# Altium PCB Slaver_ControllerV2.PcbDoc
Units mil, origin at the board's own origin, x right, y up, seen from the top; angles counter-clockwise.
Board outline 1904 x 574 mil, 4 copper layers (Top Layer, GND, PWR, Bottom Layer), stack 30.634 mil thick; 85 components, 57 nets, 252 pads, 104 vias.
Unrouted connection lines stored in the file: 1.
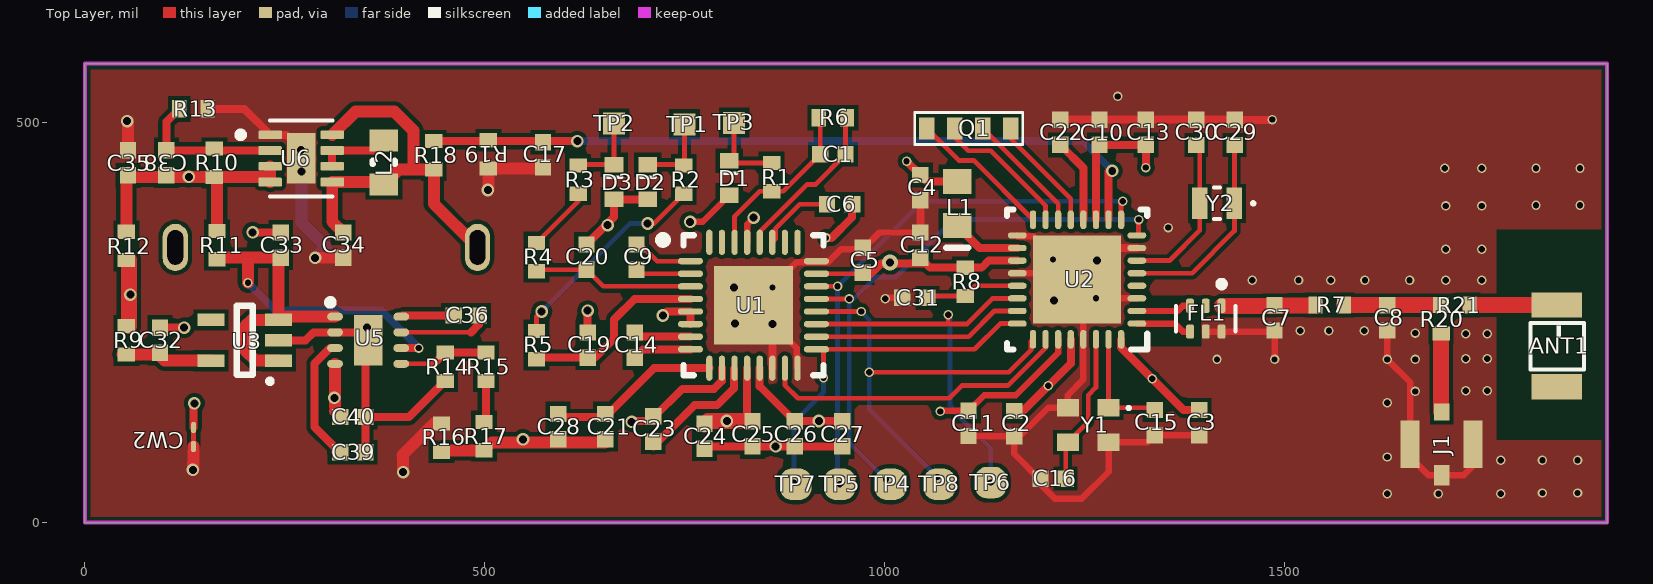
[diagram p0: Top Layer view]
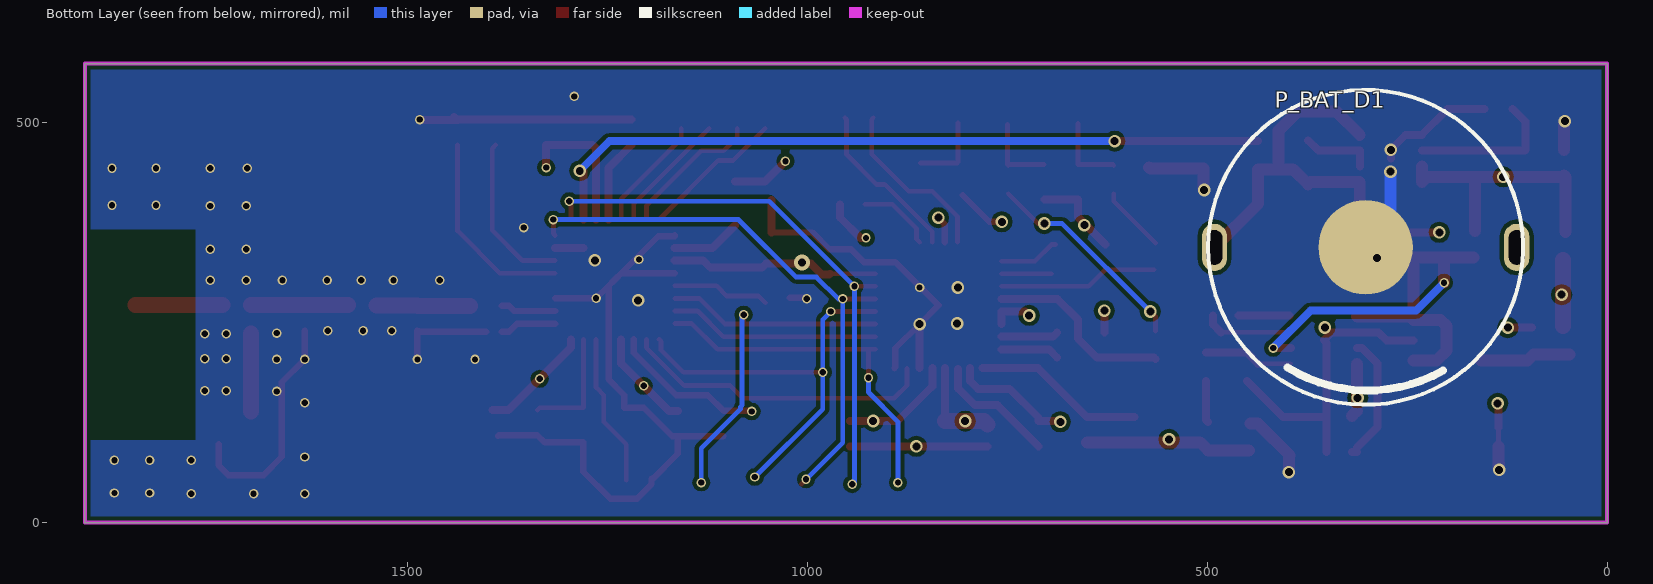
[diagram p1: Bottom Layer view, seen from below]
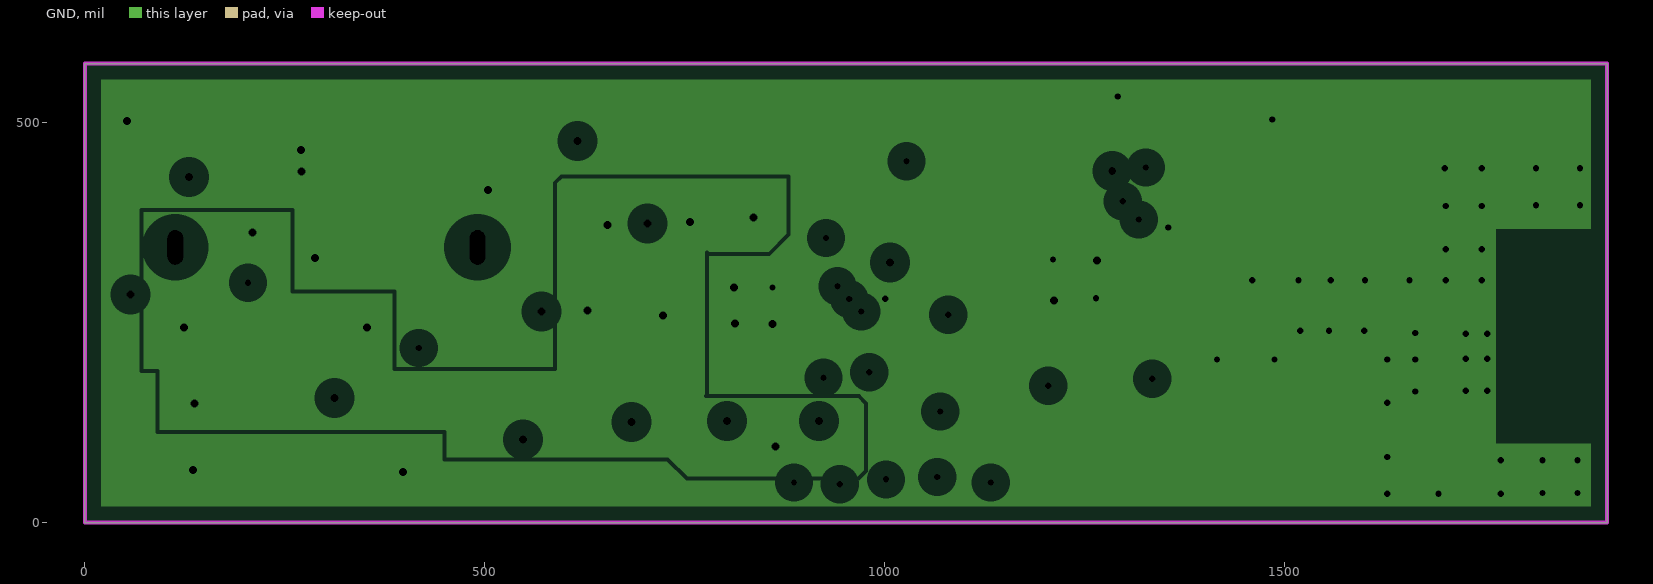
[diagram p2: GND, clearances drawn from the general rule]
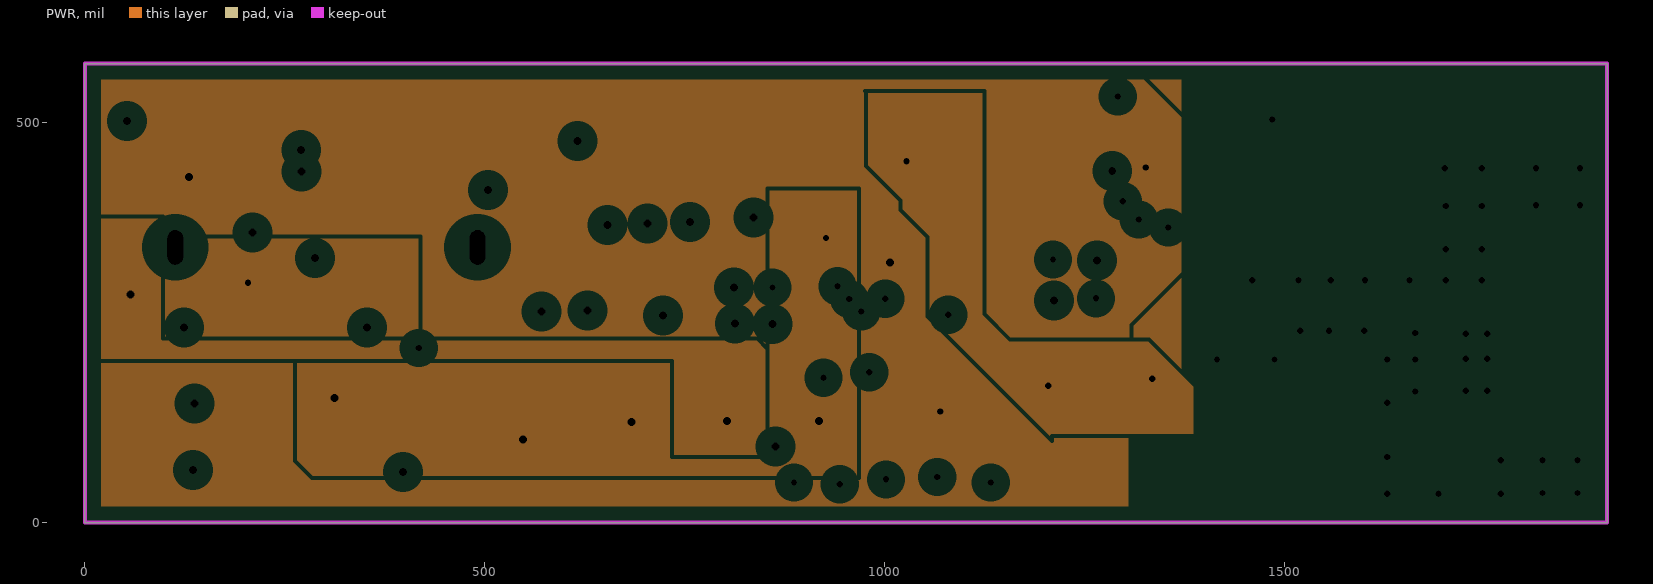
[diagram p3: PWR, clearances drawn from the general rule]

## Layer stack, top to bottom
Top Solder: solder mask 0.4, Solder Resist, Dk 3.5
Top Layer: signal copper 1.4
Dielectric 1: core 10, FR-4, Dk 4.2
GND: plane copper 1.417, net (Multiple Nets)
Dielectric 3: prepreg 5, Dk 4.2
PWR: plane copper 1.417, net (Multiple Nets)
Dielectric 2: core 10, Dk 4.2
Bottom Layer: signal copper 1.4
Bottom Solder: solder mask 0.4, Solder Resist, Dk 3.5

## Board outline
0,0 0,574 1904,574 1904,0

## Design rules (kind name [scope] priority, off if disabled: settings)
Clearance [All] p1: gap=5 ignorepadtopadclearanceinfootprint=FALSE except(0: Arc-Hole Track-Hole SMDPad-Hole THPad-Hole Via-Hole Fill-Hole Poly-Hole Region-Hole Text-Hole)
DiffPairsRouting [All] p1: maxlimit=10 minlimit=8 mostfreqgap=10 toplayer_minwidth=6 toplayer_maxwidth=15 toplayer_prefwidth=15 bottomlayer_minwidth=6 bottomlayer_maxwidth=15 bottomlayer_prefwidth=15 maxuncoupledlength=500
PlaneClearance [All] p1: clearance=20
PlaneConnect [All] p1: planeconnectstyle=Relief reliefexpansion=20 reliefentries=4 reliefconductorwidth=10 reliefairgap=10
PolygonConnect [All] p1: connectstyle=Direct reliefconductorwidth=10 reliefentries=4 polygonreliefangle="90 Angle" airgapwidth=10
RoutingVias [All] p1: holewidth=8.66 width=18.5 viastyle="Through Hole" minholewidth=7.87 minwidth=11.81 maxholewidth=28 maxwidth=50
SolderMaskExpansion [All] p1: expansion=4
Width [All] p1: maxlimit=30 minlimit=6 preferedwidth=6 minimp=50.000000 maximp=50.000000 favimp=50.000000
27 further rules are at their usual default settings.

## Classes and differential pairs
differential pair RF: +RF_P -RF_N

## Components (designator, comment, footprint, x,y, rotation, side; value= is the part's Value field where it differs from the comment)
ANT1 "2450AT18B100E" ANT_2450AT18B100E 1841,221 r270 top
C1 "CAP" CAPC0402(1005)33_L 935.58,460.66 r180 top
C2 "CAP" CAPC0402(1005)33_L 1162.38,123.73 r270 top
C3 "CAP" CAPC0402(1005)33_L 1394,125 r270 top
C4 "CAP" CAPC0402(1005)33_L 1045,419 r270 top
C5 "CAP" CAPC0402(1005)33_L 973,328 r270 top
C6 "CAP" CAPC0402(1005)33_L 944,398 r180 top
C7 "CAP" CAPC0402(1005)33_L 1488,256 r270 top
C8 "CAP" CAPC0402(1005)33_L 1629,256 r270 top
C9 "CAP" CAPC0402(1005)33_L 690,332 r270 top
C10 "CAP" CAPC0402(1005)33_L 1269,488.19 r90 top
C11 "CAP" CAPC0402(1005)33_L 1105.19,124 r270 top
C12 "CAP" CAPC0402(1005)33_L 1045,347 r90 top
C13 "CAP" CAPC0402(1005)33_L 1327,488.19 r90 top
C14 "CAP" CAPC0402(1005)33_L 687.81,222 r90 top
C15 "CAP" CAPC0402(1005)33_L 1338,125 r270 top
C16 "CAP" CAPC0402(1005)33_L 1211,55 r180 top
C17 "CAP" CAPC0402(1005)33_L 573,460 r90 top
C19 "CAP" CAPC0402(1005)33_L 628.98,222 r270 top
C20 "CAP" CAPC0402(1005)33_L 627.5,332 r270 top
C21 "CAP" CAPC0402(1005)33_L 651,120 r90 top
C22 "CAP" CAPC0402(1005)33_L 1220,488.19 r90 top
C23 "CAP" CAPC0402(1005)33_L 711,117 r270 top
C24 "CAP" CAPC0402(1005)33_L 775,108 r90 top
C25 "CAP" CAPC0402(1005)33_L 835,111 r90 top
C26 "CAP" CAPC0402(1005)33_L 887.81,111 r90 top
C27 "CAP" CAPC0402(1005)33_L 947.14,111 r90 top
C28 "CAP" CAPC0402(1005)33_L 592,120 r90 top
C29 "CAP" CAPC0402(1005)33_L 1438,488 r90 top
C30 "CAP" CAPC0402(1005)33_L 1390,488 r90 top
C31 "CAP" CAPC0402(1005)33_L 1038,281 r180 top
C32 "CAP" CAPC0402(1005)33_L 94,228 r90 top
C33 "CAP" CAPC0402(1005)33_L 245.08,347 r90 top
C34 "CAP" CAPC0402(1005)33_L 323,347 r270 top
C35 "CAP" CAPC0402(1005)33_L 54,450 r90 top
C36 "CAP" CAPC0402(1005)33_L 477,259 r0 top
C38 "CAP" CAPC0402(1005)33_L 102,450 r270 top
C39 "CAP" CAPC0402(1005)33_L 335,88 r0 top
C40 "CAP" CAPC0402(1005)33_L 335,132 r0 top
CW2 "CrossWire" CrossWire_0201 136,107 r270 top net-tie
D1 "ESD9R3.3ST5G" ESD9R3.3ST5G 806,431 r270 top
D2 "ESD9R3.3ST5G" ESD9R3.3ST5G 704,426 r270 top
D3 "ESD9R3.3ST5G" ESD9R3.3ST5G 662,426 r270 top
FL1 "2450BM14G0011T" BALUN_2450BM14G0011T 1402,255 r270 top
J1 "CONREVSMA001-SMD-G" KH-IPEX3-2020 1697,98 r270 top
L1 "" INDC1608L 1091,399 r90 top
L2 "" RESC0603(1608)_L 374.02,450.5 r90 top
P_BAT_D1 "BAT" CR927 302.17,344.2 r180 bottom locked
Q1 "JTAG" connect4 1053,493 r180 top
R1 "RES" RESC0402(1005)_L#1 859,432.02 r270 top
R2 "RES" RESC0402(1005)_L#1 749,429.02 r270 top
R3 "RES" RESC0402(1005)_L#1 617,429.02 r270 top
R4 "RES" RESC0402(1005)_L#1 565,332 r270 top
R5 "RES" RESC0402(1005)_L#1 565,222 r270 top
R6 "RES" RESC0402(1005)_L#1 935.58,506.2 r0 top
R7 "RES" RESC0402(1005)_L#1 1557,272 r0 top
R8 "RES" RESC0402(1005)_L#1 1101,301 r90 top
R9 "RES" RESC0402(1005)_L#1 52,228 r270 top
R10 "RES" RESC0402(1005)_L#1 162,450 r270 top
R11 "RES" RESC0402(1005)_L#1 165.36,347 r90 top
R12 "RES" RESC0402(1005)_L#1 52,346 r90 top
R13 "RES" RESC0402(1005)_L#1 135.83,517.43 r180 top
R14 "RES" RESC0402(1005)_L#1 450.61,194.88 r90 top
R15 "RES" RESC0402(1005)_L#1 501.8,194.88 r270 top
R16 "RES" RESC0402(1005)_L#1 446,106.17 r90 top
R17 "RES" RESC0402(1005)_L#1 499.15,108.14 r90 top
R18 "RES" RESC0402(1005)_L#1 436.41,459.37 r270 top
R19 "RES" RESC0402(1005)_L#1 504.7,460.35 r90 top
R20 "RES" RESC0402(1005)_L#2 1696.28,254 r270 top
R21 "RES" RESC0402(1005)_L#2 1714,272 r0 top
TP1 "0.7mm" "TESTPOINT 0.7" 750,498 r90 top
TP2 "0.7mm" "TESTPOINT 0.7" 662,499 r90 top
TP3 "0.7mm" "TESTPOINT 0.7" 812,500 r90 top
TP4 "1mm" "TESTPOINT 1mm" 1007.61,48 r90 top
TP5 "1mm" "TESTPOINT 1mm" 944.31,48 r90 top
TP6 "1mm" "TESTPOINT 1mm" 1133,50 r90 top
TP7 "1mm" "TESTPOINT 1mm" 889,48 r90 top
TP8 "1mm" "TESTPOINT 1mm" 1069,48 r90 top
U1 "ADS1291RIRSMT" ADS1291IRSMT 836.24,271.83 r0 top
U2 "CC2640R2FRSMR" CC2640R2F_RSM_32 1241,304 r180 top
U3 "TLV70025DCKR" SC-70 200,228 r180 top
U5 "LM27761" LM27761DSGR 354.33,228.06 r0 top
U6 "TPS61021ADSGR" SON50P200X200X80-9N 270.67,455.43 r0 top
Y1 "ECS-240-6-37B-7KM-TR" XTAL_ECS-240-6-37B-7KM-TR 1255,122 r180 top
Y2 "ECS-.327-7-16-C-TR" XTAL_ECS-.327-7-16-C-TR 1416.06,399.31 r180 top

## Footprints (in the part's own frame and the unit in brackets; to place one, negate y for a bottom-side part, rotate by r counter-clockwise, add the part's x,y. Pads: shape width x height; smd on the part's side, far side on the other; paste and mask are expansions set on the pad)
ADS1291IRSMT [mm] "QFN, 32-Leads, Body 4.00x4.00mm, Pitch 0.40mm, Thermal Pad 2.70x2.70mm, IPC Medium Density"
  oval 0.8x0.2 smd mask+0.05: 1(-2,1.4) 2(-2,1) 3(-2,0.6) 4(-2,0.2) 5(-2,-0.2) 6(-2,-0.6) 7(-2,-1) 8(-2,-1.4) 17(2,-1.4) 18(2,-1) 19(2,-0.6) 20(2,-0.2) 21(2,0.2) 22(2,0.6) 23(2,1) 24(2,1.4)
  oval 0.2x0.8 smd mask+0.05: 9(-1.4,-2) 10(-1,-2) 11(-0.6,-2) 12(-0.2,-2) 13(0.2,-2) 14(0.6,-2) 15(1,-2) 16(1.4,-2) 25(1.4,2) 26(1,2) 27(0.6,2) 28(0.2,2) 29(-0.2,2) 30(-0.6,2) 31(-1,2) 32(-1.4,2)
  rect 2.5x2.5 smd paste-0.5 mask+0.05: 33(0,0)
  silkscreen extent -3,-2.22 2.22,2.23, body extent -2.08,-2.07 2.07,2.08, height 1
ANT_2450AT18B100E [mm]
  rect 0.8x1.6 smd: 1(-1.3,0) 2(1.3,0)
  silkscreen extent -0.73,-0.84 0.75,0.86
BALUN_2450BM14G0011T [mm]
  rrect50% 0.45x0.25 smd: 1(-0.41,0.5) 2(-0.41,0) 3(-0.41,-0.5) 4(0.41,-0.5) 5(0.41,0) 6(0.41,0.5)
  silkscreen extent -1.2,-0.94 0.4,0.94
CAPC0402(1005)33_L [mm] "Chip Capacitor, Body 1.0x0.5mm, Height 0.33mm, IPC High Density"
  rect 0.52x0.52 smd: 1(-0.4,0) 2(0.4,0)
  body extent -0.55,-0.3 0.55,0.3, height 0.33
CC2640R2F_RSM_32 [mm]
  oval 0.6x0.2 smd paste+0 mask+0.051: 1(-1.9,1.4) 2(-1.9,1) 3(-1.9,0.6) 4(-1.9,0.2) 5(-1.9,-0.2) 6(-1.9,-0.6) 7(-1.9,-1) 8(-1.9,-1.4) 17(1.9,-1.4) 18(1.9,-1) 19(1.9,-0.6) 20(1.9,-0.2) 21(1.9,0.2) 22(1.9,0.6) 23(1.9,1) 24(1.9,1.4)
  oval 0.2x0.6 smd paste+0 mask+0.051: 9(-1.4,-1.9) 10(-1,-1.9) 11(-0.6,-1.9) 12(-0.2,-1.9) 13(0.2,-1.9) 14(0.6,-1.9) 15(1,-1.9) 16(1.4,-1.9) 25(1.4,1.9) 26(1,1.9) 27(0.6,1.9) 28(0.2,1.9) 29(-0.2,1.9) 30(-0.6,1.9) 31(-1,1.9) 32(-1.4,1.9)
  rect 2.8x2.8 smd paste-1.387 mask+0.051: 33(0,0)
  silkscreen extent -2.23,-2.23 2.23,2.23, body extent 0,0 0.25,0.25, height 0.25
connect4 [mm]
  rect 0.5x0.7 smd: 1(0,0) 2(-0.889,0) 3(-1.778,0) 4(-2.667,0)
  silkscreen extent -3.05,-0.51 0.38,0.51
CR927 [mm]
  oval 0.8x1.5 hole 0.5 slot 1.1 at 90 deg: 1(-4.8,0) 1(4.8,0)
  round 3 smd: 2(0,0)
  silkscreen extent -5,-5 5,5
CrossWire_0201 [mm] "Chip Resistor, Body 0.6x0.3mm, IPC High Density"
  rrect75% 0.35x0.152 smd paste-0.254 mask-0.254: 1(-0.3,0) 2(0.3,0)
  Top Layer lines w0.152: 0.3,0 -0.3,0
ESD9R3.3ST5G [mm]
  rect 0.5x0.6 smd: 1(-0.55,0) 2(0.55,0)
  silkscreen extent -0.15,-0.25 -0.15,0.25, body extent -0.4,-0.3 0.4,0.3, height 0.4
INDC1608L [mm] "Chip Inductor, Body 1.6x0.8mm, IPC High Density"
  rect 0.8x0.9 smd: 1(-0.7,0) 2(0.7,0)
  silkscreen extent -1.4,-0.35 -1.4,0.35, body extent -0.87,-0.48 0.87,0.48, height 0.55
KH-IPEX3-2020 [mm] "https://item.szlcsc.com/550999.html"
  rect 0.55x0.5 smd: 1(-1.025,0)
  rect 1.5x0.6 smd: 2(0,-1) 4(0,1)
  rect 0.65x0.5 smd: 3(0.98,0)
LM27761DSGR [mm] "QFN, 8-Leads, Body 2.00x2.00mm, Pitch 0.50mm, Thermal Pad 0.90x1.60mm, IPC Medium Density"
  oval 0.5x0.25 smd mask+0.05: 1(-1.05,0.75) 2(-1.05,0.25) 3(-1.05,-0.25) 4(-1.05,-0.75) 5(1.05,-0.75) 6(1.05,-0.25) 7(1.05,0.25) 8(1.05,0.75)
  rect 0.9x1.6 smd paste-2 mask+0.05: 9(0,0)
  silkscreen extent -1.27,1.13 -1.12,1.27, body extent -1.05,-1.05 1.05,1.05, height 0.8
RESC0402(1005)_L#1 [mm] "Chip Resistor, Body 1.0x0.5mm, IPC High Density"
  rect 0.45x0.55 smd: 1(-0.45,0) 2(0.45,0)
  body extent -0.52,-0.27 0.53,0.28, height 0.4
RESC0402(1005)_L#2 [mm] "Chip Resistor, Body 1.0x0.5mm, IPC High Density"
  rect 0.5x0.5 smd: 1(-0.45,0)
  rect 0.45x0.55 smd: 2(0.45,0)
  body extent -0.52,-0.27 0.53,0.28, height 0.4
RESC0603(1608)_L [mm] "Chip Resistor, Body 1.6x0.8mm, IPC High Density"
  rect 0.7x0.9 smd: 1(-0.7,0) 2(0.7,0)
  silkscreen extent -0.05,-0.35 0.05,0.35, body extent -0.85,-0.47 0.85,0.47, height 0.6
SC-70 [mm] "SOT23, 5-Leads, Body 1.97x2.10mm, Pitch 0.65mm, IPC Medium Density"
  rect 0.85x0.4 smd: 1(-1.075,0.65) 2(-1.075,0) 3(-1.075,-0.65) 4(1.075,-0.65) 5(1.075,0.65)
  silkscreen extent -0.83,-1.1 0.25,1.32, body extent -0.65,-1.07 0.65,1.08, height 1
SON50P200X200X80-9N [mm]
  rrect25% 0.74x0.28 smd: 1(-0.985,0.75) 2(-0.985,0.25) 3(-0.985,-0.25) 4(-0.985,-0.75) 5(0.985,-0.75) 6(0.985,-0.25) 7(0.985,0.25) 8(0.985,0.75)
  rect 0.9x1.6 smd paste-2: 9(0,0)
  silkscreen extent -2.02,-1.21 1,1.21
"TESTPOINT 0.7" [mm]
  rect 0.7x0.7 smd paste-5 mask+0.05: 1(0,0)
  body extent -0.5,-0.5 0.5,0.5, height 0.1
"TESTPOINT 1mm" [mm]
  rrect75% 1x1 smd paste-5 mask+0.05: 1(0,0)
  body extent -0.5,-0.5 0.5,0.5, height 0.1
XTAL_ECS-240-6-37B-7KM-TR [mm]
  rect 0.7x0.55 smd: 1(-0.65,-0.55) 2(0.65,-0.55) 3(0.65,0.55) 4(-0.65,0.55)
  silkscreen extent -1.34,-0.59 -1.24,-0.49
XTAL_ECS-.327-7-16-C-TR [mm]
  rect 0.5x1 smd: 1(-0.55,0) 2(0.55,0)
  silkscreen extent -1.2,-0.5 0.1,0.5

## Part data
ANT1: "2.4GHz Chip RF Antenna 2.4GHz ~ 2.5GHz 0.5dBi Solder Surface Mount"
C1 C5 C6 C9 C14 C15 C16 C17 C19 C20 C21 C22 C23 C24 C25 C26 C27 C28 C29 C30 C36 C38 C39 C40: "Capacitor General"
C2 C3 C7 C8 C10 C11 C13 C31: "CAP, CERM, 0.1 uF, 25 V, +/- 10%, X7R, 0402"
C4 C32 C33 C34 C35: "CAP, CERM, 10 uF, 25 V, +/- 20%, X5R"
C12: "CAP, CERM, 10 uF, 25 V, +/- 20%, X5R, 0603"
CW2: "Resistor in 0402 package"
FL1: "RF Balun 2.4GHz ~ 2.5GHz 50 / -Ohm 0603 _1608 Metric_"
J1: library part SMA-KH-IPEX3-2020, "Connector, SMA, Vertical, Gold, SMT"
L1: library part Inductor, "Inductor, Multilayer, Ferrite, 10 uH, 0.11 A, 0.52 ohm, SMD"
L2: library part Inductor, "110m ohm, SMD，IDC = 1.1 A"
P_BAT_D1: library part 100mil_Port2, "100 mil 2pin port"
Q1: library part CON4
R1 R2 R3 R4 R5 R6 R7 R9 R10 R11 R12 R13 R14 R15 R16 R17 R18 R19 R20 R21: "Resistor General"
R8: "RES, 100 k, 1%, 0.1 W, 0402"
TP1 TP2 TP3 TP4 TP5 TP6 TP7 TP8: library part "TESTPOINT 1mm", "1mm testpoint"
U1: library part ADS1291/1292
U2: "Imported"
U6: "3-A Boost Converter with 0.5-V Ultra Low Input Voltage"
Y1: "24MHz ?±10ppm Crystal 6pF 50 Ohms 4-SMD, No Lead,2016"
Y2: "32.768kHz ?±10ppm Crystal 7pF 90 kOhms 2-SMD, No Lead"

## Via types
v1: diameter 11.81, hole 7.87, Top Layer to Bottom Layer, tented both sides, 70 vias
v2: diameter 15.75, hole 10, Top Layer to Bottom Layer, tented both sides, 33 vias
v3: diameter 20, hole 10, Top Layer to Bottom Layer, tented both sides, 1 vias

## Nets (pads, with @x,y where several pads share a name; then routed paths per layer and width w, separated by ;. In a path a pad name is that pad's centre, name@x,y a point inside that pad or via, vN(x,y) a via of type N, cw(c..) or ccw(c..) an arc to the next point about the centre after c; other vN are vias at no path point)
2V5_A: C24.2 C25.2 R9.1 R12.1 U1.12 | length 203.9
  Top Layer w10: C25.2@828.37,126.86 U1.12
  Top Layer w20: R9.1@55,245.72 R12.1@55,328.28 ; C24.2@775,122.75 779.11,126.86 C25.2@828.37,126.86
  other v2: 803,127 57,285
3V: C33.1 R11.1 U3.1 U3.3 U5.1 U5.6 | length 651.9
  Top Layer w10: U5.6 v1(417.78,218.22)
  Top Layer w15: R11.1@167.33,331.25 204,331.25 ; v1(204,300) 204,331.25 ; U3.1 213.59,202.41 201,215 201,246 208.59,253.59 U3.3 ; U5.1 246.32,257.59 U3.3 ; 204,331.25 C33.1 242.32,328.49 U3.3
  Bottom Layer w10: v1(204,300) 239,265 371,265 v1(417.78,218.22)
-2V5_A: C6.1 C21.1 C23.1 C26.2 C27.2 C28.1 C40.1 R16.1 R17.1 U1.10 U1.13 U5.4 | length 626.1
  Top Layer w10: v2(684,126) 684.75,126.75 711,126.75 711,131 747.34,167.34 786.9,167.34 796.87,177.31 U1.10 ; U1.13 844.12,170.44 C26.2 C27.2 ; v1(927,356) 934,356 959.75,381.75 C6.1
  Top Layer w15: C40.1@312.99,139.74 C40.1@319.25,133.48 ; 312.99,145.74 U5.4 ; R16.1@447.97,90.43 R17.1 508.98,100.25 C21.1@650.48,100.25 ; v2@546.53,102.53 v2(548,104)
  other v2: 918,127 312,156
AFE_CLK: TP7.1 U1.17 U2.24 | length 446.9
  Top Layer w6: U1.17 U1.17@923,216.71 ; v1(923.84,181) 923.84,215.87 U1.17@923,216.71 ; U2.24 1144.88,248.88 1112.71,216.71 U1.17@923,216.71
  Bottom Layer w6: v1(887,50) 887,126.16 923.84,163 v1(923.84,181)
AFE_CS#: U1.18 U2.23 | length 264.5
  Top Layer w6: U1.18 1105.46,232.46 1137.63,264.63 U2.23
AFE_DRDY#: TP5.1 U1.22 U2.9 | length 699.8
  Top Layer w6: U1.22 v1(941.45,295.45) ; U2.9 1296.12,400.12 v1(1298,402)
  Bottom Layer w6: v1(944.31,48) 941.45,50.86 v1(941.45,295.45) 1048,402 v1(1298,402)
AFE_MISO: TP4.1 U1.21 U2.8 | length 717.6
  Top Layer w6: U1.21 v1(956,279.7) ; v1(1002,54) TP4.1@1007.61,48.39 ; U2.8 1318,361.31 v1(1318,379)
  Bottom Layer w6: v1(1002,54) 956,100 v1(956,279.7) 961.7,279.7 989,307 1014.46,307 1086.46,379 v1(1318,379)
AFE_MOSI: TP6.1 U1.19 U2.22 | length 512.3
  Top Layer w6: U1.19 1080,248.2 ; v1(1080,260) 1080,248.2 ; U2.22 1135.38,280.38 1103.2,248.2 1080,248.2
  Bottom Layer w6: v1(1080,260) 1082,262 1082,146.67 1083.91,144.76 1083.91,142.09 1133,93 v1(1133,50)
AFE_RESET#: U1.15 U2.26 | length 390.8
  Top Layer w6: U1.15 875.61,171.8 891.96,155.45 1081.07,155.45 1097,171.39 1154.39,171.39 1201.63,218.63 U2.26
AFE_SCK: TP8.1 U1.20 U2.25 | length 530.6
  Top Layer w6: U1.20 v1(971,263.95) ; v1(981,188) 1155.44,188 1183.22,215.78 1183.22,226.54 U2.25
  Bottom Layer w6: v1(971,263.95) 981,253.95 v1(981,188) 981,142 v1(1066,57)
BAT_SENSE: C17.2 R18.1 R19.2 U2.10 | length 929.3
  Top Layer w10: R18.1 571.67,477.08 571.75,477 v2(616,477) ; U2.10 1280.37,439.25 1281.12,440 v2(1285,440)
  Bottom Layer w10: v2(616,477) 1248,477 v2(1285,440)
DCDC_SW: L1.1 U2.18 | length 86.8
  Top Layer w10: L1.1 1119.07,343.37 U2.18
DVDD: C5.2 C10.1 C11.1 C12.1 C13.1 C35.1 C38.2 R8.2 R10.2 R11.2 R12.2 U1.23 U2.11 U2.19 U2.27 U6.3 U6.4 | length 982.2
  Top Layer w6: U1.23 C5.2@972.06,311.2
  Top Layer w8: v1(1070,139) 1070.75,139.75 C11.1 1124.83,159.39 1164.39,159.39 1217.38,212.38 U2.27
  Top Layer w10: C5.2@972.06,311.2 973,310.25 982.25,310.25 996,324 1051.75,324 1057.03,318.72 R8.2 1121.72,318.72 1130.62,327.62 U2.19 ; U2.11 1264.62,468.06 C10.1 C13.1 v1(1327,444)
  Top Layer w15: R12.2 C35.1@52,432.25 ; C35.1 C35.1@52.03,432.28 ; R11.2 165.36,428.93 R10.2 ; U6.3 U6.4 225.5,432.28 R10.2 ; C35.1@52.03,432.28 v2(130,432.28) R10.2
  other v3: 1007,325
ELE_LA: D2.1 R2.1 TP1.1 | length 97.1
  Top Layer w6: D2.1 748.08,447.65 R2.1 750,447.73 TP1.1
ELE_RA: D3.1 R3.1 TP2.1 | length 96.7
  Top Layer w6: R3.1 617.92,447.65 D3.1 TP2.1
ELE_REF: D1.1 R1.1 TP3.1 | length 96.7
  Top Layer w6: TP3.1 812,450.72 812.06,450.65 812.98,449.73 R1.1
FB: C38.1 R10.1 R13.2 U6.2 | length 188.4
  Top Layer w10: R13.2 102,501.32 C38.1 102.48,465.27 U6.2
GND: C2.2 C3.2 C4.2 C5.1 C7.2 C8.2 C10.2 C11.2 C12.2 C13.2 C15.2 C16.2 C17.1 C22.2 C29.2 C30.2 C31.2 C34.2 C35.2 CW2.2 FL1.5 FL1.6 J1.2 J1.3 J1.4 P_BAT_D1.2 R13.1 R16.2 R19.1 U1.14 U1.16 U1.24 U1.33 U2.3 U2.7 U2.17 U2.20 U2.29 U2.33 U6.1 U6.9 Y1.2 Y1.4 | length 2633
  Top Layer w8: U1.16 890.24,194.21 890.24,217.83 v2(859.87,248.2) U1.33 890.24,325.82 929.82,325.82 945.75,341.75 973,341.75 994,362.75 C12.2 ; v1(1001,280) 1000,281 C31.2 ; C11.2 1105.46,107.98 C2.2 ; U2.20 U2.33@1233.13,311.87 ; U2.17 1166.2,357.99 1187.01,357.99 U2.33@1233.13,311.87 ; C16.2 C16.2@1195.25,53 ; U2.3 v1(1264.62,280.38) U2.33@1248.87,296.13 ; C3.2@1387,108.25 1386,109.25 C15.2 1329.09,100.35 Y1.4 1280.59,63.59 1247,30 1213.28,30 1195.25,48.02 C16.2@1195.25,53 ; FL1.5 FL1.6 1486.61,238.86 C7.2 v1@1488,203 ; C8.2 v1(1629,204) 1657.63,175.37 J1.2 1657.63,82.2 1680.42,59.42 J1.3 1724.42,59.42 1736.37,71.37 J1.4 ; C2.2 1169.35,107.98 1205.02,143.65 Y1.2 1229.41,159.41 1248.87,178.87 U2.29 U2.33@1248.87,296.13 ; C2.2 1162.38,85.87 C16.2@1195.25,53 ; U2.33@1233.13,311.87 U2.33 U2.33@1248.87,296.13
  Top Layer w10: R13.1 199.41,517.43 U6.1 251.95,484.95 v2(270.67,466.24) U6.9 ; U1.14 v2(859.87,248.2) ; C12.2 C4.2 ; C22.2 C10.2 C13.2 1438.94,503.94 C29.2@1442.06,507.06 ; U2.33@1280.37,343.37 U2.7 ; C29.2 1484.75,503.75 v1(1485,504)
  Top Layer w15: v2(53,502) 54,501 C35.2 ; 135,74.27 v2(135,66) 136,67 CW2.2 ; v2(288,331) 288.25,331.25 C34.2 ; v2(398,63) 398,83 397,84 436.89,123.89 R16.2 ; v2(504,416) 504.7,416.7 R19.1 571.38,442.63 C17.1
  Bottom Layer w15: v2(271,439) 271,375.37 P_BAT_D1.2@301.68,344.68 ; v2(288,331) P_BAT_D1.2@301.2,344.2
  other v1: 1629,36 1693,36 1771,36 1823,37 1867,37 1771,78 1823,78 1867,78 1629,82 1629,150 1664,164 1727,165 1754,165 1416,204 1488,204 1664,204 1727,205 1754,205 1727,236 1754,236 1664,237 1520,240 1556,240 1600,240 860,294 1460,303 1518,303 1558.43,303 1601,303 1656.85,303 1702,303 1747,303 1211,329 1702,342 1747,342 1355,369 1702,396 1747,396 1815,397 1870,397 1701,443 1747,443 1815,443 1870,443 1292,533
  other v2: 813,249 1212,278 812,294 1266,328
GND_A: C19.1 C20.1 C24.1 C25.1 C26.1 C27.1 C32.2 C33.2 C39.2 C40.2 CW2.1 D1.2 D2.2 D3.2 R14.1 U1.5 U1.6 U1.29 U3.2 U5.2 U5.9 | length 940
  Top Layer w8: v2(757,376.16) 772.81,376.16 D1.2 ; U1.29 828.37,373.29 v2(836.39,381.31)
  Top Layer w10: C32.2 v2(124.25,243.75) ; CW2.1 136,147.89 135.94,147.94 v2(137,149) ; v2(210,363) 210.25,362.75 C33.2 ; U3.2 276,228 285.91,237.91 U5.2 344.49,237.91 U5.9 350.75,224.48 C40.2 ; C39.2 C40.2 ; R14.1 405.45,132 C40.2 ; C20.1 662,382.25 D3.2 D2.2 ; C19.1 v2(628.98,265.02) ; v2(723,259) 727.95,263.95 U1.5 U1.6 ; C24.1@775,95.25 C26.1 C27.1
  Bottom Layer w8: v2@835.32,381.31 v2(836.39,381.31)
  Bottom Layer w10: v2(124.25,243.75) v2@125,243
  other v2: 864,95.25 353,244 654,372
IN1N: R3.2 R4.1 | length 83.1
  Top Layer w6: R4.1 617,401.72 R3.2
IN1P: R2.2 R5.1 | length 265.3
  Top Layer w6: R5.1 565,258 v2@571,264 ; v2(704,374) 711.7,374 R2.2
  Bottom Layer w6: v2(571.46,264) 681.46,374 v2(704,374)
JTAG_RST: C31.1 R8.1 U2.21 | length 122.2
  Top Layer w6: C31.1@1052.75,275 1061.03,283.28 R8.1 1113.84,296.13 U2.21
JTAG_TCKC: Q1.3 U2.14 | length 153.3
  Top Layer w6: Q1.3 1217.38,398.62 U2.14
JTAG_TMSC: Q1.4 U2.13 | length 145.3
  Top Layer w6: Q1.4 1158,480 1233.13,404.87 U2.13
NetANT1_1: ANT1.1 R21.2 | length 109.4
  Top Layer w10: ANT1.1@1840.82,272 ANT1.1
  Top Layer w20: R21.2 ANT1.1@1840.82,272
NetC1_1: C1.1 R6.2 U1.28 | length 206.9
  Top Layer w6: U1.28 844.12,363.51 903.61,423 913.96,423 951.33,460.37 C1.1 951.33,504.23 R6.2
NetC6_2: C6.2 U1.27 | length 95.7
  Top Layer w6: U1.27 863.68,354.38 863.68,367.51 894.16,398 C6.2
NetC7_1: C7.1 FL1.1 R7.1 | length 117.1
  Top Layer w10: R7.1@1539.03,271.75 R7.1
  Top Layer w20: FL1.1@1422.51,271.14 1487.39,271.14 C7.1 R7.1@1539.03,271.75
NetC8_1: C8.1 R7.2 R20.1 R21.1 | length 121.6
  Top Layer w20: R7.2 R21.1
NetC9_1: C9.1 U1.1 | length 76.1
  Top Layer w6: C9.1 694.98,347.75 715.78,326.94 U1.1
NetC9_2: C9.2 U1.2 | length 62.4
  Top Layer w6: C9.2@695.06,311.2 U1.2
NetC14_1: C14.1 U1.8 | length 74
  Top Layer w10: C14.1 698.27,216.71 U1.8
NetC14_2: C14.2 U1.7 | length 71.9
  Top Layer w10: C14.2 693.1,232.46 U1.7
NetC19_2: C19.2 R5.2 U1.4 | length 237.8
  Top Layer w10: R5.2 566.97,206.25 C19.2 638.25,206.25 662,230 662,254 687.7,279.7 U1.4
NetC20_2: C20.2 R4.2 U1.3 | length 199.2
  Top Layer w6: R4.2@566.97,316.25 C20.2 648.3,295.45 U1.3
NetC22_1: C22.1 U2.12 | length 105.6
  Top Layer w10: C22.1 1248.87,443.57 U2.12
NetC32_1: C32.1 R9.2 U3.5 | length 113.9
  Top Layer w15: R9.2@47,210.28 92.03,210.28 99.91,202.41 U3.5
NetC36_1: C36.1 U5.8 | length 64.2
  Top Layer w10: U5.8@397.08,259 C36.1
NetC36_2: C36.2 U5.7 | length 112.4
  Top Layer w6: U5.7 482.91,237.91
  Top Layer w10: 482.91,237.91 492.75,247.75 C36.2
NetC39_1: C39.1 U5.3 | length 155.4
  Top Layer w10: C39.1@313,88 C39.1 ; C39.1@313,94 287.43,119.57 287.43,199 306.65,218.22 U5.3
NetJ1_1: J1.1 R20.2 | length 98.2
  Top Layer w10: J1.1@1696.28,139.07 J1.1
  Top Layer w20: J1.1@1696.28,139.07 R20.2
NetL2_2: L2.2 U6.6 U6.7 | length 89.6
  Top Layer w10: U6.6 U6.7 361.22,465.27 L2.2
NetR14_2: R14.2 R15.1 U5.5 | length 112
  Top Layer w6: U5.5 436.55,198.54
  Top Layer w10: 436.55,198.54 R14.2 R15.1
NetR15_2: R15.2 R17.2 | length 52.4
  Top Layer w10: R17.2 501.8,128.5 R15.2
RF_N: FL1.3 U2.2 | length 69.2
  Top Layer w8: U2.2 1366.88,264.63 1373.39,271.14 FL1.3
RF_P: FL1.4 U2.1 | length 70.7
  Top Layer w8: U2.1 1363.37,248.88 1373.39,238.86 FL1.4
RLDOUT: C1.2 R1.2 R6.1 U1.30 | length 218.2
  Top Layer w6: U1.30 812.62,383 843.92,414.3 R1.2 873.48,414.3 C1.2 919.83,504.23 R6.1
U0_RX: Q1.1 U2.16 | length 180.2
  Top Layer w6: Q1.1 1093,453 1111.68,453 U2.16
U0_TX: Q1.2 U2.15 | length 177.7
  Top Layer w6: Q1.2 1088,482 1105,465 1133,465 1201.63,396.37 U2.15
VBAT_IN: C34.1 L2.1 P_BAT_D1.1 R18.2 U6.5 U6.8 | length 496.8
  Top Layer w15: U6.8 338.5,514 387.25,514 411,490.25 411,441.65 ; C34.1 309.45,376.3 U6.5 371.06,425.9 L2.1 392.72,441.65 411,441.65 ; P_BAT_D1.1@491.14,344.2 436.41,398.94 R18.2 411,441.65
VCAP1: C23.2 U1.11 | length 155.4
  Top Layer w10: C23.2@711,95.25 762.73,146.98 790.97,146.98 811.87,167.89 U1.11@811.87,192.34
VDDR: C2.1 C3.1 C4.1 L1.2 U2.28 U2.32 | length 339.9
  Top Layer w10: v1(1027.75,452) C4.1 1053.19,426.56 L1.2 ; C2.1 1173.48,139.48 1233.13,199.13 U2.28 ; U2.32 1296.12,218.88 1374.25,140.75 C3.1
  other v1: 1205,171 1335.19,179.81
VREF_P: C21.2 C28.2 U1.9 | length 215.4
  Top Layer w10: C28.2@591.14,131.75 650.48,131.75 711.82,193.09 U1.9
X24M_N: C16.1 U2.30 Y1.3 | length 191.9
  Top Layer w6: C16.1@1226.75,53 1226.75,97.69 Y1.3 1255,125.94 1255,159.4 1264.62,169.02 U2.30
X24M_P: C15.1 U2.31 Y1.1 | length 144.2
  Top Layer w6: U2.31 1280.37,143.87 Y1.1 1335.09,143.65 C15.1
X32K_Q1: C29.1 U2.5 Y2.1 | length 251.5
  Top Layer w6: U2.5 1384.87,311.87 1437.72,364.72 Y2.1 1437.72,471.97 C29.1
X32K_Q2: C30.1 U2.6 Y2.2 | length 202.9
  Top Layer w6: U2.6 1356.62,327.62 1394.41,365.41 Y2.2 1394.41,467.84 C30.1
pads on no net: ANT1.2 FL1.2 U1.25 U1.26 U1.31 U1.32 U2.4 U3.4

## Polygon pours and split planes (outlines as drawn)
GND on Bottom Layer "Top Layer-No Net" (solid, remove dead copper, pour order 0): 0,574 0,0 1904,0 1904,574
GND on Top Layer "Top Layer-No Net" (solid, remove dead copper, pour order 2): 1,0 1,573 0,574 1904,574 1904,0
GND on GND (split plane): 1883.9,367 1765,367 1765,99 1883.9,99 1883.9,20.1 20.1,20.1 20.1,553.9 1883.9,553.9
GND_A on GND (split plane): 877.45,361.06 854.94,338.55 781.06,338.55 779.8,339.8 778.98,340.36 778,340.55 777.02,340.36 776.2,339.8 775.64,338.98 775.45,338 775.45,160.06 775.2,159.8 774.64,158.98 774.45,158 774.64,157.02 775.2,156.2 776.02,155.64 777,155.45 966.94,155.45 974.45,147.94 974.45,65.51 966.49,57.55 754.06,57.55 730.8,80.8 729.98,81.36 729,81.55 452.55,81.55 452.55,113 452.36,113.98 451.8,114.8 450.98,115.36 450,115.55 93.55,115.55 93.55,189.64 93.36,190.62 92.8,191.45 91.98,192 91,192.19 73.55,192.19 73.55,388.45 257.45,388.45 257.45,289 257.64,288.02 258.2,287.2 259.02,286.64 260,286.45 384.45,286.45 384.45,192 384.64,191.02 385.2,190.2 386.02,189.64 387,189.45 588,189.45 588.98,189.64 589.8,190.2 590.36,191.02 590.55,192 590.55,423.94 597.06,430.45 877.45,430.45
DVDD on PWR (split plane): 1372,506.4 1372,313.6 1307.2,248.8 1306.65,247.98 1306.45,247 1306.45,231.75 1157.86,231.75 1127.55,262.06 1127.55,540 1127.35,540.98 1126.8,541.8 1125.98,542.36 1125,542.55 976,542.55 975.02,542.36 974.2,541.8 973.65,540.98 973.45,540 973.65,539.02 974.2,538.2 974.45,537.94 974.45,446 974.65,445.02 975.2,444.2 1017.45,401.94 1017.45,391 1017.65,390.02 1018.2,389.2 1051.45,355.94 1051.45,258 1051.65,257.02 1052.2,256.2 1207.92,100.47 1208.75,99.92 1209.72,99.73 1210.7,99.92 1211.53,100.47 1212.08,101.3 1212.27,102.28 1212.27,105.45 1305.45,105.45 1305.45,20.1 20.1,20.1 20.1,199.45 260.45,199.45 260.45,77 260.64,76.02 261.2,75.2 282.2,54.2 283.02,53.64 284,53.45 968,53.45 968.98,53.64 969.8,54.2 970.35,55.02 970.55,56 970.55,418 970.35,418.98 969.8,419.8 968.98,420.36 968,420.55 854,420.55 853.02,420.36 852.2,419.8 851.64,418.98 851.45,418 851.45,223.15 842.8,231.8 841.98,232.36 841,232.55 422.55,232.55 422.55,358 422.36,358.98 421.8,359.8 420.98,360.36 420,360.55 100.55,360.55 100.55,383 100.36,383.98 99.8,384.8 98.98,385.36 98,385.55 20.1,385.55 20.1,553.9 1324.49,553.9
3V on PWR (split plane): 417.45,232.55 100.55,232.55 100.55,355.45 417.45,355.45
2V5_A on PWR (split plane): 95.45,230 95.64,229.02 96.2,228.2 97.02,227.64 98,227.45 839.94,227.45 851.45,215.94 851.45,84.55 737.19,84.55 737.19,202 737,202.98 736.45,203.8 735.62,204.36 734.64,204.55 20.1,204.55 20.1,380.45 95.45,380.45
-2V5_A on PWR (split plane): 965.45,58.55 285.06,58.55 265.55,78.06 265.55,199.45 732.1,199.45 732.1,82 732.29,81.02 732.84,80.2 733.67,79.64 734.64,79.45 854,79.45 854.98,79.64 855.8,80.2 856.36,81.02 856.55,82 856.55,217 856.36,217.98 856.16,218.27 856.36,218.57 856.55,219.55 856.55,415.45 965.45,415.45
VDDR on PWR (split plane): 1122.45,261 1122.65,260.02 1123.2,259.2 1155,227.39 1155.83,226.84 1156.8,226.65 1329.75,226.65 1386.45,169.94 1386.45,110.55 1209.72,110.55 1208.75,110.36 1207.92,109.8 1207.37,108.98 1207.25,108.36 1056.55,259.06 1056.55,357 1056.35,357.98 1055.8,358.8 1022.55,392.06 1022.55,403 1022.35,403.98 1021.8,404.8 979.55,447.06 979.55,537.45 1122.45,537.45
no net on PWR (split plane): 1372,513.6 1331.7,553.9 1372,553.9
no net on PWR (split plane): 1372,191.6 1332.61,231 1331.78,231.55 1330.8,231.75 1311.55,231.75 1311.55,245.94 1372,306.4

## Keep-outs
Keep-Out Layer:
  the board outline again, w5

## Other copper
Top Layer:
  pour cut-out: 1765,103 1904,103 1904,363 1903,364 1904,365 1904,367 1765,367
  pour cut-out: 1395.81,284.06 1310,284.06 1310,220.16 1396.72,220.16
Bottom Layer:
  pour cut-out: 1765,367 1904,367 1904,103 1765,103
GND (plane layer: these items are gaps in the copper):
  pour cut-out: 1765,367 1904,367 1904,99 1765,99
  lines w5: 71,189.64 91,189.64 91,113 123,113 450,113 450,79 729,79 753,55 967.55,55 977,64.45 977,149 968,158 777,158 778,159 778,338 780,336 856,336 880,360 880,433 596,433 588,425 588,192 387,192 387,289 260,289 260,391 71,391 71,189.64
PWR (plane layer: these items are gaps in the copper):
  pour cut-out: 1307,109 1307,1 1903,1 1903,575 1372,575 1372,188 1388,172 1387.5,171.5 1387.5,109.5
  lines w5: 0,194 8,202 734.64,202 734.64,82 854,82 854,217 841,230 98,230 98,383 0,383 0,358 ; 98,358 420,358 420,232.55 ; 263,199.45 263,77 284,56 968,56 968,418 854,418 854,219.55 ; 1020,540 1125,540 1125,261 1156.8,229.2 1330.8,229.2 1389,171 1389,109 1388,108 1209.72,108 1209.72,102.28 1054,258 1054,357 1020,391 1020,403 977,446 977,539 976,540 1024,540 ; 1308,1 1308,108 ; 1308,574 1374.72,507.28 1374.72,312.72 1309,247 1309,229.2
